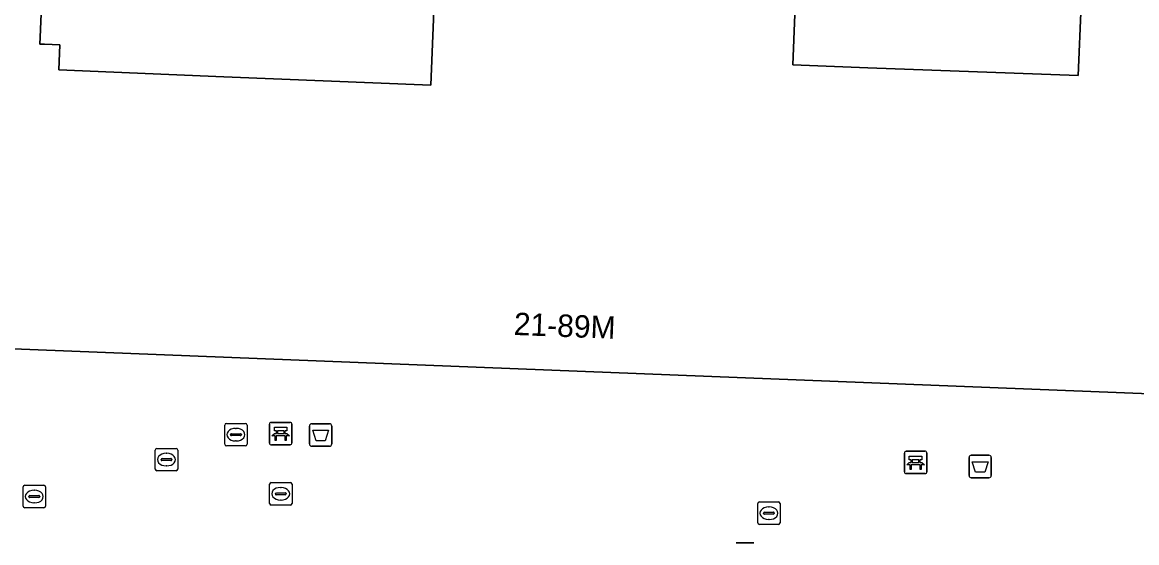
# Model space of a CAD drawing. Extents: x 160888 to 161385, y 386490 to 386908.
# Drawn here: x 161220.29 to 161269.97, y 386833.87 to 386857.07 of the extents above; entities that cross this region are included whole.
import ezdxf

# ---------------------------------------------------------------- set-up
doc = ezdxf.new("R2010")
doc.units = 0
for name, color, linetype in [('IMGEO_Afvalbak', 7, 'Continuous'), ('IMGEO_Bank', 7, 'Continuous'), ('IMGEO_Brandkraan', 7, 'Continuous'), ('IMGEO_Erf', 7, 'Continuous'), ('IMGEO_Kolk', 7, 'Continuous'), ('IMGEO_Pand', 7, 'Continuous'), ('IMGEO_Pand_nummerreeks', 7, 'Continuous'), ('IMGEO_Reclamebord', 7, 'Continuous'), ('IMGEO_Rioolput', 7, 'Continuous'), ('IMGEO_Voetgangersgebied_open', 7, 'Continuous')]:
    doc.layers.add(name, color=color, linetype=linetype)

msp = doc.modelspace()

# ---------------------------------------------------------------- linework, layer by layer
at = {"layer": 'IMGEO_Afvalbak'}
for p, q in [((161233.09, 386838.273), (161233.09, 386839.073)), ((161233.09, 386839.073), (161233.09, 386838.273)), ((161233.19, 386839.173), (161233.98, 386839.173)), ((161233.98, 386839.173), (161233.19, 386839.173)), ((161234.08, 386839.073), (161234.08, 386838.273)), ((161234.08, 386838.273), (161234.08, 386839.073)), ((161233.98, 386838.173), (161233.19, 386838.173)), ((161233.19, 386838.173), (161233.98, 386838.173)), ((161262.495, 386836.869), (161262.495, 386837.669)), ((161262.495, 386837.669), (161262.495, 386836.869)), ((161262.595, 386837.769), (161263.385, 386837.769)), ((161263.385, 386837.769), (161262.595, 386837.769)), ((161263.485, 386837.669), (161263.485, 386836.869)), ((161263.485, 386836.869), (161263.485, 386837.669)), ((161263.385, 386836.769), (161262.595, 386836.769)), ((161262.595, 386836.769), (161263.385, 386836.769))]:
    msp.add_line(p, q, dxfattribs=at)
for points in [[(161233.233, 386838.887), (161233.937, 386838.887), (161233.788, 386838.417), (161233.382, 386838.417), (161233.233, 386838.887)], [(161262.638, 386837.483), (161263.342, 386837.483), (161263.193, 386837.013), (161262.787, 386837.013), (161262.638, 386837.483)]]:
    msp.add_lwpolyline(points, dxfattribs=at)
for centre, start, end in [((161233.19, 386839.073), 90, 180), ((161233.19, 386839.073), 90, 180), ((161233.98, 386839.073), 0, 90), ((161233.98, 386839.073), 360, 90), ((161233.19, 386838.273), 180, 270), ((161233.19, 386838.273), 180, 270), ((161233.98, 386838.273), 270, 0), ((161233.98, 386838.273), 270, 0), ((161262.595, 386837.669), 90, 180), ((161262.595, 386837.669), 90, 180), ((161263.385, 386837.669), 0, 90), ((161263.385, 386837.669), 360, 90), ((161262.595, 386836.869), 180, 270), ((161262.595, 386836.869), 180, 270), ((161263.385, 386836.869), 270, 0), ((161263.385, 386836.869), 270, 0)]:
    msp.add_arc(centre, 0.1, start, end, dxfattribs=at)
at = {"layer": 'IMGEO_Bank'}
for p, q in [((161231.308, 386838.312), (161231.308, 386839.153)), ((161231.308, 386839.153), (161231.308, 386838.312)), ((161231.383, 386839.237), (161232.224, 386839.237)), ((161232.224, 386839.237), (161231.383, 386839.237)), ((161231.617, 386838.743), (161231.617, 386838.849)), ((161231.661, 386838.849), (161231.661, 386838.743)), ((161231.949, 386838.855), (161231.667, 386838.855)), ((161231.955, 386838.743), (161231.955, 386838.849)), ((161231.999, 386838.849), (161231.999, 386838.743)), ((161232.308, 386839.162), (161232.308, 386838.321)), ((161232.308, 386838.321), (161232.308, 386839.162)), ((161232.005, 386838.635), (161231.612, 386838.635)), ((161231.667, 386838.737), (161231.949, 386838.737)), ((161232.233, 386838.237), (161231.392, 386838.237)), ((161231.392, 386838.237), (161232.233, 386838.237)), ((161259.612, 386837.027), (161259.612, 386837.868)), ((161259.612, 386837.868), (161259.612, 386837.027)), ((161259.687, 386837.952), (161260.528, 386837.952)), ((161260.528, 386837.952), (161259.687, 386837.952)), ((161260.612, 386837.877), (161260.612, 386837.036)), ((161260.612, 386837.036), (161260.612, 386837.877)), ((161260.309, 386837.35), (161259.916, 386837.35)), ((161259.921, 386837.458), (161259.921, 386837.564)), ((161259.965, 386837.564), (161259.965, 386837.458)), ((161260.253, 386837.57), (161259.971, 386837.57)), ((161259.971, 386837.452), (161260.253, 386837.452)), ((161260.259, 386837.458), (161260.259, 386837.564)), ((161260.303, 386837.564), (161260.303, 386837.458)), ((161260.537, 386836.952), (161259.696, 386836.952)), ((161259.696, 386836.952), (161260.537, 386836.952))]:
    msp.add_line(p, q, dxfattribs=at)
for points in [[(161231.611, 386838.855), (161231.525, 386838.855), (161231.525, 386839.016), (161232.088, 386839.016), (161232.088, 386838.855), (161232.005, 386838.855)], [(161231.555, 386838.635), (161231.413, 386838.635), (161231.525, 386838.737), (161231.611, 386838.737)], [(161231.605, 386838.628), (161231.605, 386838.421), (161231.562, 386838.421), (161231.562, 386838.628)], [(161232.005, 386838.737), (161232.088, 386838.737), (161232.2, 386838.635), (161232.061, 386838.635)], [(161232.055, 386838.628), (161232.055, 386838.421), (161232.011, 386838.421), (161232.011, 386838.628)], [(161259.859, 386837.35), (161259.717, 386837.35), (161259.829, 386837.452), (161259.915, 386837.452)], [(161259.915, 386837.57), (161259.829, 386837.57), (161259.829, 386837.731), (161260.392, 386837.731), (161260.392, 386837.57), (161260.309, 386837.57)], [(161259.909, 386837.343), (161259.909, 386837.136), (161259.866, 386837.136), (161259.866, 386837.343)], [(161260.309, 386837.452), (161260.392, 386837.452), (161260.504, 386837.35), (161260.365, 386837.35)], [(161260.359, 386837.343), (161260.359, 386837.136), (161260.315, 386837.136), (161260.315, 386837.343)]]:
    msp.add_lwpolyline(points, dxfattribs=at)
for centre, radius, start, end in [((161231.386, 386839.159), 0.0779, 92.4484, 184.2845), ((161231.386, 386839.159), 0.0779, 92.4484, 184.2845), ((161231.61, 386838.848), 0.00671, 2.8957, 87.1043), ((161231.667, 386838.848), 0.00671, 92.8957, 177.1043), ((161231.949, 386838.848), 0.00671, 2.8957, 87.1043), ((161232.006, 386838.848), 0.00671, 92.8957, 177.1043), ((161232.23, 386839.159), 0.0779, 2.4484, 94.2845), ((161232.23, 386839.159), 0.0779, 2.4484, 94.2845), ((161231.386, 386838.315), 0.0779, 182.4484, 274.2845), ((161231.386, 386838.315), 0.0779, 182.4484, 274.2845), ((161231.555, 386838.628), 0.00671, 2.8957, 87.1043), ((161231.612, 386838.628), 0.00671, 92.8957, 177.1043), ((161231.61, 386838.744), 0.00671, 272.8957, 357.1043), ((161231.667, 386838.744), 0.00671, 182.8957, 267.1043), ((161231.949, 386838.744), 0.00671, 272.8957, 357.1043), ((161232.006, 386838.744), 0.00671, 182.8957, 267.1043), ((161232.004, 386838.628), 0.00671, 2.8957, 87.1043), ((161232.061, 386838.628), 0.00671, 92.8957, 177.1043), ((161232.23, 386838.315), 0.0779, 272.4484, 4.2845), ((161232.23, 386838.315), 0.0779, 272.4484, 4.2845), ((161259.69, 386837.874), 0.0779, 92.4484, 184.2845), ((161259.69, 386837.874), 0.0779, 92.4484, 184.2845), ((161260.534, 386837.874), 0.0779, 2.4484, 94.2845), ((161260.534, 386837.874), 0.0779, 2.4484, 94.2845), ((161259.859, 386837.343), 0.00671, 2.8957, 87.1043), ((161259.916, 386837.343), 0.00671, 92.8957, 177.1043), ((161259.914, 386837.563), 0.00671, 2.8957, 87.1043), ((161259.914, 386837.459), 0.00671, 272.8957, 357.1043), ((161259.971, 386837.563), 0.00671, 92.8957, 177.1043), ((161259.971, 386837.459), 0.00671, 182.8957, 267.1043), ((161260.253, 386837.563), 0.00671, 2.8957, 87.1043), ((161260.253, 386837.459), 0.00671, 272.8957, 357.1043), ((161260.31, 386837.563), 0.00671, 92.8957, 177.1043), ((161260.31, 386837.459), 0.00671, 182.8957, 267.1043), ((161260.308, 386837.343), 0.00671, 2.8957, 87.1043), ((161260.365, 386837.343), 0.00671, 92.8957, 177.1043), ((161259.69, 386837.03), 0.0779, 182.4484, 274.2845), ((161259.69, 386837.03), 0.0779, 182.4484, 274.2845), ((161260.534, 386837.03), 0.0779, 272.4484, 4.2845), ((161260.534, 386837.03), 0.0779, 272.4484, 4.2845)]:
    msp.add_arc(centre, radius, start, end, dxfattribs=at)
at = {"layer": 'IMGEO_Brandkraan'}
for p, q in [((161229.31, 386838.262), (161229.31, 386839.114)), ((161229.385, 386839.188), (161230.237, 386839.188)), ((161229.798, 386838.968), (161229.823, 386838.968)), ((161230.311, 386839.114), (161230.311, 386838.262)), ((161229.569, 386838.682), (161229.569, 386838.694)), ((161230.007, 386838.645), (161229.609, 386838.645)), ((161229.612, 386838.731), (161230.01, 386838.731)), ((161229.821, 386838.408), (161229.796, 386838.408)), ((161230.053, 386838.694), (161230.053, 386838.682)), ((161230.237, 386838.188), (161229.385, 386838.188))]:
    msp.add_line(p, q, dxfattribs=at)
for points in [[(161229.31, 386838.262), (161229.31, 386839.114)], [(161229.385, 386839.188), (161230.237, 386839.188)], [(161230.311, 386839.114), (161230.311, 386838.262)], [(161230.237, 386838.188), (161229.385, 386838.188)]]:
    msp.add_lwpolyline(points, dxfattribs=at)
for centre, radius, start, end in [((161229.387, 386839.112), 0.0765, 91.552, 178.448), ((161229.387, 386839.112), 0.0765, 91.552, 178.448), ((161230.235, 386839.112), 0.0765, 1.552, 88.448), ((161230.235, 386839.112), 0.0765, 1.552, 88.448), ((161229.609, 386838.691), 0.0403, 85.8775, 175.7526), ((161229.606, 386838.681), 0.0366, 178.938, 274.7102), ((161230.01, 386838.688), 0.043, 264.8664, 352.4533), ((161230.014, 386838.693), 0.0386, 1.7309, 96.639), ((161229.387, 386838.264), 0.0765, 181.552, 268.448), ((161229.387, 386838.264), 0.0765, 181.552, 268.448), ((161230.235, 386838.264), 0.0765, 271.552, 358.448), ((161230.235, 386838.264), 0.0765, 271.552, 358.448)]:
    msp.add_arc(centre, radius, start, end, dxfattribs=at)
for centre, major_axis, ratio, start_param, end_param in [((161229.797, 386838.688), (-0.387, 0.002), 0.722429, 4.712389, 7.853982), ((161229.822, 386838.688), (-0.39, 0.002), 0.717154, 1.570796, 4.712389)]:
    msp.add_ellipse(centre, major_axis=major_axis, ratio=ratio, start_param=start_param, end_param=end_param, dxfattribs=at)
at = {"layer": 'IMGEO_Erf'}
msp.add_lwpolyline([(161278.689, 386885.003), (161268.594, 386885.414), (161249.896, 386886.171), (161239.793, 386886.567), (161222.396, 386887.248), (161222.369, 386886.248), (161221.375, 386860.939), (161221.275, 386860.943), (161221.078, 386856.403), (161221.066, 386856.099), (161221.271, 386856.091), (161221.965, 386856.062), (161221.919, 386854.943), (161229.279, 386854.644), (161238.505, 386854.269), (161238.86, 386863.105), (161248.886, 386860.967), (161254.82, 386859.706), (161254.804, 386859.3), (161254.641, 386855.168), (161257.979, 386855.044), (161267.366, 386854.695), (161267.493, 386857.839), (161277.574, 386857.417)], dxfattribs=at)
at = {"layer": 'IMGEO_Kolk'}
for p, q in [((161231.311, 386835.627), (161231.311, 386836.479)), ((161231.386, 386836.553), (161232.238, 386836.553)), ((161231.799, 386836.333), (161231.824, 386836.333)), ((161232.312, 386836.479), (161232.312, 386835.627)), ((161231.57, 386836.047), (161231.57, 386836.059)), ((161232.008, 386836.01), (161231.61, 386836.01)), ((161231.613, 386836.096), (161232.011, 386836.096)), ((161232.054, 386836.059), (161232.054, 386836.047)), ((161232.238, 386835.553), (161231.386, 386835.553)), ((161231.822, 386835.773), (161231.797, 386835.773)), ((161253.072, 386834.761), (161253.072, 386835.613)), ((161253.147, 386835.687), (161253.999, 386835.687)), ((161253.56, 386835.467), (161253.585, 386835.467)), ((161254.073, 386835.613), (161254.073, 386834.761)), ((161253.331, 386835.181), (161253.331, 386835.193)), ((161253.769, 386835.144), (161253.371, 386835.144)), ((161253.374, 386835.23), (161253.772, 386835.23)), ((161253.583, 386834.907), (161253.558, 386834.907)), ((161253.815, 386835.193), (161253.815, 386835.181)), ((161253.999, 386834.687), (161253.147, 386834.687))]:
    msp.add_line(p, q, dxfattribs=at)
for points in [[(161231.311, 386835.627), (161231.311, 386836.479)], [(161231.386, 386836.553), (161232.238, 386836.553)], [(161232.312, 386836.479), (161232.312, 386835.627)], [(161232.238, 386835.553), (161231.386, 386835.553)], [(161253.072, 386834.761), (161253.072, 386835.613)], [(161253.147, 386835.687), (161253.999, 386835.687)], [(161254.073, 386835.613), (161254.073, 386834.761)], [(161253.999, 386834.687), (161253.147, 386834.687)]]:
    msp.add_lwpolyline(points, dxfattribs=at)
for centre, radius, start, end in [((161231.388, 386836.477), 0.0765, 91.552, 178.448), ((161231.388, 386836.477), 0.0765, 91.552, 178.448), ((161232.236, 386836.477), 0.0765, 1.552, 88.448), ((161232.236, 386836.477), 0.0765, 1.552, 88.448), ((161231.61, 386836.056), 0.0403, 85.8775, 175.7526), ((161231.607, 386836.046), 0.0366, 178.938, 274.7102), ((161232.011, 386836.053), 0.043, 264.8664, 352.4533), ((161232.015, 386836.058), 0.0386, 1.7309, 96.639), ((161231.388, 386835.629), 0.0765, 181.552, 268.448), ((161231.388, 386835.629), 0.0765, 181.552, 268.448), ((161232.236, 386835.629), 0.0765, 271.552, 358.448), ((161232.236, 386835.629), 0.0765, 271.552, 358.448), ((161253.149, 386835.611), 0.0765, 91.552, 178.448), ((161253.149, 386835.611), 0.0765, 91.552, 178.448), ((161253.997, 386835.611), 0.0765, 1.552, 88.448), ((161253.997, 386835.611), 0.0765, 1.552, 88.448), ((161253.371, 386835.19), 0.0403, 85.8775, 175.7526), ((161253.368, 386835.18), 0.0366, 178.938, 274.7102), ((161253.772, 386835.187), 0.043, 264.8664, 352.4533), ((161253.776, 386835.192), 0.0386, 1.7309, 96.639), ((161253.149, 386834.763), 0.0765, 181.552, 268.448), ((161253.149, 386834.763), 0.0765, 181.552, 268.448), ((161253.997, 386834.763), 0.0765, 271.552, 358.448), ((161253.997, 386834.763), 0.0765, 271.552, 358.448)]:
    msp.add_arc(centre, radius, start, end, dxfattribs=at)
for centre, major_axis, ratio, start_param, end_param in [((161231.798, 386836.053), (-0.387, 0.002), 0.722429, 4.712389, 7.853982), ((161231.823, 386836.053), (-0.39, 0.002), 0.717154, 1.570796, 4.712389), ((161253.559, 386835.187), (-0.387, 0.002), 0.722429, 4.712389, 7.853982), ((161253.584, 386835.187), (-0.39, 0.002), 0.717154, 1.570796, 4.712389)]:
    msp.add_ellipse(centre, major_axis=major_axis, ratio=ratio, start_param=start_param, end_param=end_param, dxfattribs=at)
at = {"layer": 'IMGEO_Pand'}
for points in [[(161238.86, 386863.105), (161238.505, 386854.269), (161229.279, 386854.644), (161221.919, 386854.943), (161221.965, 386856.062), (161221.271, 386856.091), (161221.066, 386856.099), (161221.078, 386856.403), (161221.275, 386860.943), (161221.375, 386860.939), (161222.369, 386886.248), (161210.581, 386886.706), (161210.559, 386886.386), (161210.538, 386886.09)], [(161208.047, 386882.906), (161205.549, 386883.004), (161205.23, 386883.017), (161203.943, 386850.322), (161203.707, 386843.159), (161282.19, 386840.045), (161283.986, 386839.974), (161284.468, 386852.014), (161284.901, 386852.005), (161284.908, 386852.43), (161283.395, 386852.488), (161277.385, 386852.718), (161277.574, 386857.417), (161267.493, 386857.839), (161267.366, 386854.695), (161257.979, 386855.044), (161254.641, 386855.168), (161254.804, 386859.3), (161254.82, 386859.706), (161248.886, 386860.967), (161238.86, 386863.105)]]:
    msp.add_lwpolyline(points, dxfattribs=at)
at = {"layer": 'IMGEO_Reclamebord'}
for p, q in [((161252.108, 386833.873), (161252.898, 386833.873)), ((161252.898, 386833.873), (161252.108, 386833.873))]:
    msp.add_line(p, q, dxfattribs=at)
at = {"layer": 'IMGEO_Rioolput'}
for p, q in [((161226.214, 386837.151), (161226.214, 386838.003)), ((161226.289, 386838.077), (161227.141, 386838.077)), ((161226.702, 386837.857), (161226.727, 386837.857)), ((161227.215, 386838.003), (161227.215, 386837.151)), ((161226.473, 386837.571), (161226.473, 386837.583)), ((161226.911, 386837.534), (161226.513, 386837.534)), ((161226.516, 386837.62), (161226.914, 386837.62)), ((161226.957, 386837.583), (161226.957, 386837.571)), ((161227.141, 386837.077), (161226.289, 386837.077)), ((161226.725, 386837.297), (161226.7, 386837.297)), ((161220.321, 386835.504), (161220.321, 386836.356)), ((161220.396, 386836.43), (161221.248, 386836.43)), ((161221.322, 386836.356), (161221.322, 386835.504)), ((161220.58, 386835.924), (161220.58, 386835.936)), ((161221.018, 386835.887), (161220.62, 386835.887)), ((161220.623, 386835.973), (161221.021, 386835.973)), ((161220.809, 386836.21), (161220.834, 386836.21)), ((161221.064, 386835.936), (161221.064, 386835.924)), ((161221.248, 386835.43), (161220.396, 386835.43)), ((161220.832, 386835.65), (161220.807, 386835.65))]:
    msp.add_line(p, q, dxfattribs=at)
for points in [[(161226.214, 386837.151), (161226.214, 386838.003)], [(161226.289, 386838.077), (161227.141, 386838.077)], [(161227.215, 386838.003), (161227.215, 386837.151)], [(161227.141, 386837.077), (161226.289, 386837.077)], [(161220.321, 386835.504), (161220.321, 386836.356)], [(161220.396, 386836.43), (161221.248, 386836.43)], [(161221.322, 386836.356), (161221.322, 386835.504)], [(161221.248, 386835.43), (161220.396, 386835.43)]]:
    msp.add_lwpolyline(points, dxfattribs=at)
for centre, radius, start, end in [((161226.291, 386838.001), 0.0765, 91.552, 178.448), ((161226.291, 386838.001), 0.0765, 91.552, 178.448), ((161227.139, 386838.001), 0.0765, 1.552, 88.448), ((161227.139, 386838.001), 0.0765, 1.552, 88.448), ((161226.513, 386837.58), 0.0403, 85.8775, 175.7526), ((161226.51, 386837.57), 0.0366, 178.938, 274.7102), ((161226.914, 386837.577), 0.043, 264.8664, 352.4533), ((161226.918, 386837.582), 0.0386, 1.7309, 96.639), ((161226.291, 386837.153), 0.0765, 181.552, 268.448), ((161226.291, 386837.153), 0.0765, 181.552, 268.448), ((161227.139, 386837.153), 0.0765, 271.552, 358.448), ((161227.139, 386837.153), 0.0765, 271.552, 358.448), ((161220.398, 386836.354), 0.0765, 91.552, 178.448), ((161220.398, 386836.354), 0.0765, 91.552, 178.448), ((161221.246, 386836.354), 0.0765, 1.552, 88.448), ((161221.246, 386836.354), 0.0765, 1.552, 88.448), ((161220.62, 386835.933), 0.0403, 85.8775, 175.7526), ((161220.617, 386835.923), 0.0366, 178.938, 274.7102), ((161221.021, 386835.93), 0.043, 264.8664, 352.4533), ((161221.025, 386835.935), 0.0386, 1.7309, 96.639), ((161220.398, 386835.506), 0.0765, 181.552, 268.448), ((161220.398, 386835.506), 0.0765, 181.552, 268.448), ((161221.246, 386835.506), 0.0765, 271.552, 358.448), ((161221.246, 386835.506), 0.0765, 271.552, 358.448)]:
    msp.add_arc(centre, radius, start, end, dxfattribs=at)
for centre, major_axis, ratio, start_param, end_param in [((161226.701, 386837.577), (-0.387, 0.002), 0.722429, 4.712389, 7.853982), ((161226.726, 386837.577), (-0.39, 0.002), 0.717154, 1.570796, 4.712389), ((161220.808, 386835.93), (-0.387, 0.002), 0.722429, 4.712389, 7.853982), ((161220.833, 386835.93), (-0.39, 0.002), 0.717154, 1.570796, 4.712389)]:
    msp.add_ellipse(centre, major_axis=major_axis, ratio=ratio, start_param=start_param, end_param=end_param, dxfattribs=at)
at = {"layer": 'IMGEO_Voetgangersgebied_open'}
msp.add_lwpolyline([(161128.442, 386835.301), (161139.684, 386834.849), (161143.958, 386834.674), (161161.282, 386833.963), (161170.867, 386833.628), (161190.117, 386832.93), (161199.627, 386832.585), (161199.621, 386832.448), (161201.804, 386832.359), (161216.339, 386831.766), (161223.504, 386831.473), (161238.036, 386830.88), (161252.467, 386830.291), (161259.736, 386829.994), (161269.188, 386829.608), (161281.723, 386829.096), (161281.825, 386831.496), (161282.087, 386837.641), (161282.13, 386838.652), (161282.19, 386840.045), (161203.707, 386843.159), (161196.993, 386842.62), (161194.586, 386842.427), (161120.067, 386845.369)], dxfattribs=at)

# ---------------------------------------------------------------- texts
at = {"layer": 'IMGEO_Pand_nummerreeks'}
msp.add_text('21-89M', height=1, rotation=357.7254, dxfattribs=at).set_placement((161242.186, 386843.134))

doc.saveas('drawing.dxf')
